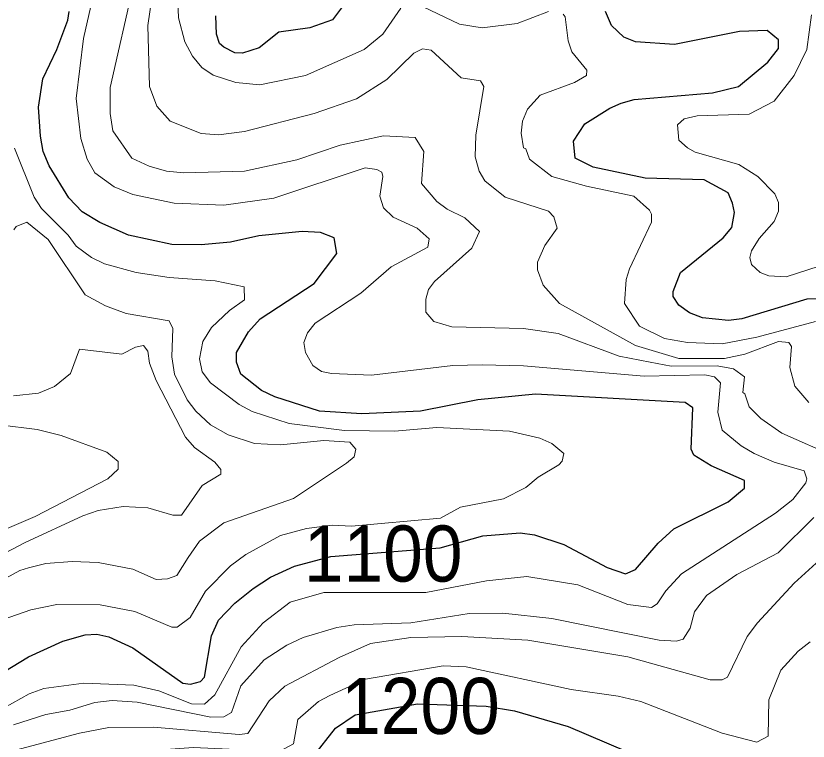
# Model space of a CAD drawing. Extents: x 423 to 448.8, y 7456.3 to 7484.
# Drawn here: x 427.288 to 428.418, y 7466.443 to 7467.476 of the extents above; entities that cross this region are included whole.
import ezdxf
from ezdxf.enums import TextEntityAlignment as Align

# ---------------------------------------------------------------- set-up
doc = ezdxf.new("R2010")
doc.units = 0
doc.header["$LTSCALE"] = 0.032
doc.layers.add('1', color=7, linetype='Continuous', lineweight=25)
doc.layers.add('2', color=7, linetype='Continuous', lineweight=13)
doc.layers.add('61', color=7, linetype='Continuous')

msp = doc.modelspace()

# ---------------------------------------------------------------- linework, layer by layer
at = {"layer": '1'}
for points in [[(427.7568, 7467.4934), (427.7398, 7467.4709), (427.7073, 7467.4593), (427.6632, 7467.4532), (427.6354, 7467.4307), (427.6114, 7467.423), (427.6006, 7467.4238), (427.5851, 7467.4315), (427.5789, 7467.4369), (427.5743, 7467.4501), (427.5735, 7467.4764)], [(427.2053, 7466.5018), (427.3067, 7466.5629), (427.3554, 7466.5853), (427.3871, 7466.5946), (427.4041, 7466.5954), (427.4211, 7466.5915), (427.4552, 7466.5761), (427.5263, 7466.5258), (427.5372, 7466.5242), (427.5518, 7466.5281), (427.5573, 7466.5343), (427.5673, 7466.5931), (427.5774, 7466.6155), (427.6006, 7466.6395), (427.6269, 7466.6603), (427.6516, 7466.6766), (427.6857, 7466.6921), (427.7375, 7466.706), (427.8933, 7466.7184), (427.954, 7466.7357), (428.0074, 7466.74), (428.0275, 7466.7369), (428.0693, 7466.723), (428.1312, 7466.6905), (428.1575, 7466.6813), (428.1714, 7466.6874), (428.2039, 7466.7253), (428.2263, 7466.7454), (428.3036, 7466.7841), (428.3268, 7466.8035), (428.3268, 7466.8143), (428.2797, 7466.8352), (428.2549, 7466.8506), (428.2511, 7466.8592), (428.2534, 7466.9179), (428.2426, 7466.9257), (428.0291, 7466.9373), (427.9471, 7466.9295), (427.8651, 7466.9133), (427.7816, 7466.9094), (427.7213, 7466.9133), (427.6578, 7466.9334), (427.6385, 7466.9427), (427.6091, 7466.9659), (427.6029, 7466.9829), (427.6029, 7466.9968), (427.6199, 7467.0262), (427.6369, 7467.0447), (427.7135, 7467.095), (427.746, 7467.1376), (427.7421, 7467.16), (427.7228, 7467.1678), (427.6965, 7467.1693), (427.6346, 7467.1631), (427.5944, 7467.1538), (427.5526, 7467.15), (427.5109, 7467.1507), (427.449, 7467.1639), (427.408, 7467.1817), (427.3832, 7467.1971), (427.3639, 7467.2173), (427.3361, 7467.2629), (427.3275, 7467.283), (427.3237, 7467.3047), (427.3206, 7467.3464), (427.3268, 7467.3867), (427.3469, 7467.4284), (427.3624, 7467.4702), (427.3647, 7467.4825)], [(428.0855, 7467.2737), (428.0832, 7467.2977), (428.0995, 7467.3224), (428.135, 7467.3449), (428.1513, 7467.3518), (428.1699, 7467.3573), (428.2812, 7467.3665), (428.3184, 7467.3758), (428.3601, 7467.4106), (428.3756, 7467.4299), (428.3756, 7467.4424), (428.3593, 7467.4555), (428.3199, 7467.4539), (428.2271, 7467.4354), (428.1714, 7467.4392), (428.1551, 7467.4462), (428.1373, 7467.4624), (428.1289, 7467.4826)], [(428.4344, 7467.0734), (428.4158, 7467.0726), (428.323, 7467.0448), (428.3044, 7467.0425), (428.2673, 7467.0463), (428.2488, 7467.0533), (428.2333, 7467.0641), (428.2255, 7467.0765), (428.2255, 7467.0835), (428.2356, 7467.1105), (428.2967, 7467.16), (428.3091, 7467.1747), (428.3129, 7467.1964), (428.3098, 7467.2095), (428.3037, 7467.2242), (428.2696, 7467.2428), (428.1853, 7467.2451), (428.1111, 7467.2606), (428.0855, 7467.2737)], [(427.2649, 7466.3107), (427.2958, 7466.3402), (427.3345, 7466.361), (427.384, 7466.3765), (427.4181, 7466.3812), (427.5325, 7466.3912), (427.6485, 7466.3966), (427.681, 7466.4036), (427.7112, 7466.4198), (427.744, 7466.4616), (427.7722, 7466.4804), (427.8609, 7466.4963), (427.959, 7466.4927), (427.9991, 7466.4862), (428.0755, 7466.4639), (428.1884, 7466.416), (428.2441, 7466.4028), (428.2696, 7466.4005), (428.2735, 7466.4036), (428.4112, 7466.4044), (428.4297, 7466.4113)]]:
    msp.add_lwpolyline(points, dxfattribs=at)
at = {"layer": '2'}
for points in [[(428.4189, 7466.9257), (428.3988, 7466.9488), (428.3918, 7466.9752), (428.3942, 7467.0053), (428.3903, 7467.0108), (428.3756, 7467.0123), (428.3276, 7466.9945), (428.2983, 7466.9883), (428.2333, 7466.9883), (428.1714, 7467.0069), (428.0631, 7467.0664), (428.0399, 7467.0927), (428.0322, 7467.1144), (428.0322, 7467.1252), (428.0422, 7467.1492), (428.06, 7467.1739), (428.0554, 7467.1902), (428.0477, 7467.1979), (427.9858, 7467.218), (427.9571, 7467.2413), (427.9486, 7467.2551), (427.9432, 7467.2753), (427.944, 7467.3062), (427.9556, 7467.3758), (427.9509, 7467.3836), (427.9231, 7467.3882), (427.8806, 7467.4276), (427.8682, 7467.4292), (427.8558, 7467.423), (427.8172, 7467.3859), (427.7738, 7467.358), (427.7135, 7467.3372), (427.6145, 7467.3116), (427.5774, 7467.307), (427.5526, 7467.3085), (427.5085, 7467.3263), (427.4892, 7467.3479), (427.4791, 7467.3758), (427.4768, 7467.4625), (427.4946, 7467.5862)], [(428.4576, 7466.8475), (428.3802, 7466.8816), (428.3501, 7466.9025), (428.3338, 7466.9195), (428.3276, 7466.938), (428.3245, 7466.9396), (428.3268, 7466.962), (428.3113, 7466.9734), (428.2878, 7466.9775), (428.2224, 7466.9772), (428.1923, 7466.9829), (428.1482, 7466.9914), (428.0616, 7467.0239), (428.0121, 7467.0309), (427.91, 7467.0332), (427.8844, 7467.0409), (427.8728, 7467.054), (427.8728, 7467.0726), (427.8767, 7467.0866), (427.8852, 7467.0981), (427.9386, 7467.1453), (427.9494, 7467.1693), (427.9285, 7467.1886), (427.903, 7467.201), (427.8883, 7467.2119), (427.8667, 7467.2374), (427.8698, 7467.283), (427.8574, 7467.3031), (427.8125, 7467.3054), (427.7506, 7467.2923), (427.6888, 7467.2714), (427.6145, 7467.2552), (427.5279, 7467.2528), (427.5031, 7467.2552), (427.4784, 7467.2621), (427.4536, 7467.2737), (427.4265, 7467.3124), (427.4227, 7467.3372), (427.4227, 7467.3743), (427.4567, 7467.5228)], [(427.8372, 7467.4872), (427.8117, 7467.4501), (427.7847, 7467.4284), (427.7011, 7467.3913), (427.6362, 7467.3781), (427.6021, 7467.3812), (427.5697, 7467.392), (427.5534, 7467.4029), (427.5403, 7467.4191), (427.5294, 7467.4393), (427.5201, 7467.4733), (427.5186, 7467.5228)], [(427.7011, 7466.9968), (427.6988, 7467.0108), (427.7042, 7467.0247), (427.7151, 7467.0386), (427.78, 7467.0811), (427.8233, 7467.119), (427.8759, 7467.1469), (427.8775, 7467.1585), (427.8605, 7467.1739), (427.8264, 7467.1894), (427.8125, 7467.2026), (427.8071, 7467.2196), (427.8117, 7467.2474), (427.8102, 7467.2536), (427.8032, 7467.2575), (427.7862, 7467.2598), (427.6563, 7467.2165), (427.5851, 7467.2064), (427.514, 7467.2095), (427.4552, 7467.2219), (427.4288, 7467.2327), (427.401, 7467.2528), (427.3902, 7467.2722), (427.3809, 7467.3016), (427.3747, 7467.3588), (427.3848, 7467.4439), (427.3979, 7467.5011)], [(428.0476, 7467.4826), (428.0028, 7467.4655), (427.9533, 7467.4593), (427.9208, 7467.4647), (427.8581, 7467.4942)], [(428.4282, 7467.0409), (428.3447, 7467.0185), (428.2952, 7467.0092), (428.2457, 7467.0108), (428.2132, 7467.0169), (428.1775, 7467.034), (428.1559, 7467.0664), (428.1582, 7467.1005), (428.1629, 7467.116), (428.1946, 7467.1825), (428.1946, 7467.194), (428.1915, 7467.1995), (428.1691, 7467.2196), (428.1018, 7467.2335), (428.0523, 7467.2474), (428.0206, 7467.2722), (428.0151, 7467.2869), (428.012, 7467.2884), (428.0089, 7467.3093), (428.0105, 7467.3263), (428.0175, 7467.3433), (428.036, 7467.3635), (428.0848, 7467.3812), (428.1018, 7467.3913), (428.1025, 7467.399), (428.0809, 7467.4253), (428.0755, 7467.4408), (428.0716, 7467.4748), (428.0685, 7467.4787)], [(428.4227, 7467.4779), (428.4158, 7467.4284), (428.398, 7467.3913), (428.3694, 7467.3549), (428.3338, 7467.3364), (428.2596, 7467.334), (428.241, 7467.3294), (428.2317, 7467.3209), (428.2333, 7467.2992), (428.2456, 7467.2884), (428.2565, 7467.2822), (428.3191, 7467.2644), (428.3462, 7467.2474), (428.3702, 7467.2227), (428.3756, 7467.2103), (428.3756, 7467.1979), (428.3694, 7467.1832), (428.3477, 7467.1593), (428.3369, 7467.1414), (428.3346, 7467.1322), (428.3369, 7467.1221), (428.3493, 7467.1105), (428.3617, 7467.1059), (428.3864, 7467.1043), (428.4483, 7467.1244)], [(427.2479, 7466.6085), (427.3098, 7466.6302), (427.3469, 7466.6379), (427.4088, 7466.6371), (427.4583, 7466.6279), (427.5109, 7466.6055), (427.5186, 7466.6055), (427.5371, 7466.6194), (427.5588, 7466.6565), (427.5944, 7466.6929), (427.6161, 7466.7091), (427.6656, 7466.7361), (427.7027, 7466.7462), (427.7398, 7466.7509), (427.7668, 7466.7494), (427.8937, 7466.7609), (427.9224, 7466.7764), (427.9834, 7466.788), (428.0152, 7466.8042), (428.0329, 7466.8189), (428.0623, 7466.8367), (428.067, 7466.8421), (428.0693, 7466.853), (428.0523, 7466.8669), (428.0353, 7466.8746), (427.992, 7466.8847), (427.8883, 7466.8901), (427.828, 7466.8847), (427.7568, 7466.8855), (427.6779, 7466.8955), (427.6253, 7466.9125), (427.6068, 7466.9226), (427.5658, 7466.9535), (427.5541, 7466.969), (427.5503, 7466.9876), (427.5549, 7467.0123), (427.5673, 7467.0324), (427.5929, 7467.0564), (427.6145, 7467.0718), (427.6137, 7467.0904), (427.5727, 7467.0989), (427.507, 7467.1035), (427.4598, 7467.1105), (427.415, 7467.1229), (427.3964, 7467.1322), (427.3747, 7467.1484), (427.3631, 7467.1639), (427.3252, 7467.2018), (427.3144, 7467.218), (427.2865, 7467.2877)], [(427.4884, 7466.6735), (427.5047, 7466.6743), (427.5178, 7466.6789), (427.534, 7466.7045), (427.5503, 7466.7277), (427.5851, 7466.7539), (427.6841, 7466.7887), (427.7599, 7466.839), (427.7707, 7466.8483), (427.773, 7466.8591), (427.7646, 7466.8692), (427.7274, 7466.8715), (427.6656, 7466.8653), (427.6284, 7466.8669), (427.5913, 7466.8792), (427.5658, 7466.8939), (427.5449, 7466.9133), (427.5325, 7466.9295), (427.5147, 7466.9659), (427.5109, 7466.9906), (427.5124, 7467.0308), (427.507, 7467.0417), (427.4459, 7467.0525), (427.4165, 7467.0633), (427.3871, 7467.0788), (427.3345, 7467.1577), (427.3043, 7467.1824), (427.2888, 7467.1762), (427.2858, 7467.1716)], [(427.2254, 7466.6859), (427.302, 7466.7261), (427.384, 7466.764), (427.4057, 7466.7717), (427.4413, 7466.7772), (427.4768, 7466.7756), (427.5124, 7466.7648), (427.5247, 7466.7648), (427.5542, 7466.8073), (427.5805, 7466.8235), (427.5805, 7466.8298), (427.5719, 7466.8406), (427.5433, 7466.8615), (427.5302, 7466.8761), (427.4884, 7466.9566), (427.4791, 7466.9814), (427.4768, 7466.9984), (427.4706, 7467.0069), (427.459, 7467.0045), (427.4397, 7466.9945), (427.3793, 7467.0015), (427.3662, 7466.9667), (427.3438, 7466.9481), (427.3206, 7466.9388), (427.285, 7466.9349)], [(427.1999, 7466.4507), (427.3074, 7466.5103), (427.3283, 7466.518), (427.3856, 7466.5258), (427.4567, 7466.5227), (427.4923, 7466.5149), (427.5387, 7466.4964), (427.5572, 7466.4956), (427.572, 7466.5088), (427.6098, 7466.5776), (427.6408, 7466.6116), (427.6795, 7466.641), (427.7274, 7466.655), (427.8729, 7466.6549), (427.9595, 7466.6712), (428.0167, 7466.6774), (428.0894, 7466.6658), (428.1606, 7466.6379), (428.1946, 7466.6333), (428.2023, 7466.6387), (428.2147, 7466.6573), (428.2371, 7466.6812), (428.371, 7466.7679), (428.3957, 7466.7872), (428.4142, 7466.8112), (428.4158, 7466.8166), (428.4119, 7466.8282), (428.3694, 7466.8406), (428.3408, 7466.853), (428.3222, 7466.8638), (428.2952, 7466.8862), (428.289, 7466.9118), (428.2928, 7466.9535), (428.2843, 7466.962), (428.2704, 7466.9651), (428.1838, 7466.9628), (428.0121, 7466.9775), (427.9533, 7466.979), (427.9115, 7466.9782), (427.7955, 7466.9643), (427.7383, 7466.9666), (427.7243, 7466.9697), (427.712, 7466.9782), (427.7011, 7466.9968)], [(427.2726, 7466.7446), (427.316, 7466.7632), (427.4196, 7466.8166), (427.4343, 7466.8305), (427.4343, 7466.8413), (427.4181, 7466.8545), (427.3531, 7466.8785), (427.3191, 7466.887), (427.2649, 7466.8939)], [(428.2727, 7466.6503), (428.316, 7466.6805), (428.3748, 7466.7114), (428.4259, 7466.7617)], [(427.2665, 7466.4244), (427.3794, 7466.4546), (427.4211, 7466.4623), (427.4846, 7466.4631), (427.6068, 7466.4523), (427.6191, 7466.4539), (427.6493, 7466.5003), (427.6718, 7466.5211), (427.7491, 7466.5621), (427.794, 7466.5822), (427.8512, 7466.5907), (427.9239, 7466.5923), (428.0183, 7466.5869), (428.1606, 7466.5629), (428.2781, 7466.5304), (428.2951, 7466.5304), (428.3028, 7466.5343), (428.3307, 7466.5923), (428.3454, 7466.6117), (428.398, 7466.6681), (428.4815, 7466.7439)], [(427.2324, 7466.6526), (427.2943, 7466.6859), (427.3067, 7466.6897), (427.3314, 7466.6959), (427.3686, 7466.699), (427.4057, 7466.6975), (427.4552, 7466.6882), (427.4884, 7466.6735)], [(427.285, 7466.4662), (427.3314, 7466.4809), (427.3655, 7466.4871), (427.401, 7466.4979), (427.4258, 7466.501), (427.4614, 7466.4987), (427.5666, 7466.477), (427.5851, 7466.4778), (427.5959, 7466.484), (427.6091, 7466.5219), (427.6424, 7466.559), (427.6748, 7466.5799), (427.698, 7466.5907), (427.746, 7466.6047), (427.7708, 7466.6085), (427.8512, 7466.6116), (427.9347, 7466.6248), (427.9827, 7466.6255), (428.0523, 7466.6178), (428.2054, 7466.5869), (428.2302, 7466.5854), (428.2394, 7466.5884), (428.2495, 7466.6039), (428.2557, 7466.6271), (428.2727, 7466.6503)], [(427.2618, 7466.3703), (427.2966, 7466.3904), (427.3113, 7466.3997), (427.3438, 7466.4128), (427.4103, 7466.4245), (427.5418, 7466.4338), (427.664, 7466.4283), (427.6841, 7466.4391), (427.6903, 7466.474), (427.7197, 7466.4995), (427.7359, 7466.508), (427.787, 7466.5312), (427.8976, 7466.5505), (427.9301, 7466.549), (428.0801, 7466.5165), (428.1467, 7466.5072), (428.1791, 7466.4995), (428.2952, 7466.4546), (428.3447, 7466.4415), (428.3609, 7466.45), (428.3617, 7466.5018), (428.3787, 7466.5443), (428.4034, 7466.5714), (428.4204, 7466.5846)]]:
    msp.add_lwpolyline(points, dxfattribs=at)

# ---------------------------------------------------------------- texts
at = {"layer": '61', "width": 0.95}
for s, p in [('1100', (427.812, 7466.6703)), ('1200', (427.8651, 7466.4532))]:
    msp.add_text(s, height=0.08, dxfattribs=at).set_placement(p, align=Align.CENTER)

doc.saveas('drawing.dxf')
